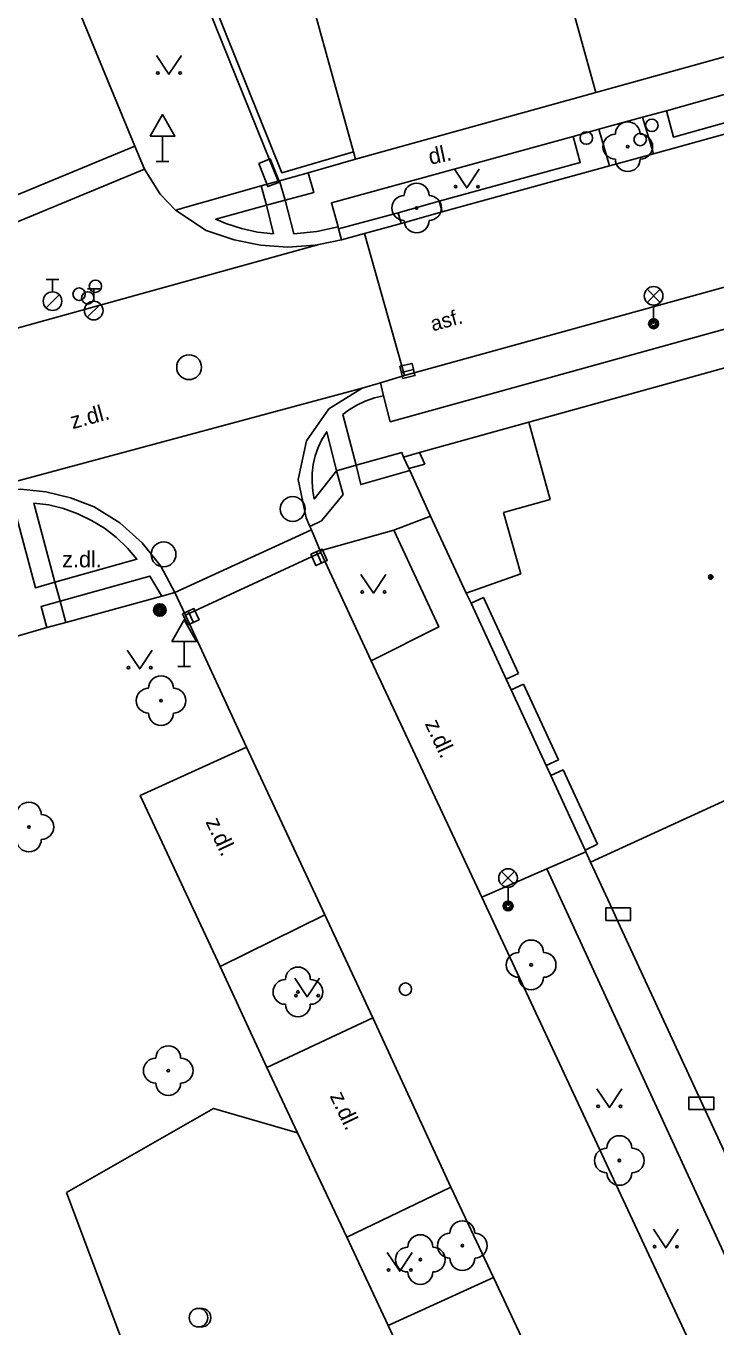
# Model space of a CAD drawing. Extents: x -595546 to -593986, y -1160845 to -1159202.
# Drawn here: x -595314.5 to -595286.7, y -1160633.9 to -1160581.5 of the extents above; entities that cross this region are included whole.
import ezdxf

# ---------------------------------------------------------------- set-up
doc = ezdxf.new("R2010")
doc.units = 0
for name, color, linetype in [('Level 22', 7, 'Continuous'), ('Level 24', 7, 'Continuous'), ('Level 25', 7, 'Continuous'), ('Level 27', 7, 'Continuous'), ('Level 28', 7, 'Continuous'), ('Level 33', 7, 'Continuous'), ('Level 34', 7, 'Continuous'), ('Level 36', 7, 'Continuous'), ('Level 39', 7, 'Continuous'), ('Specificka linie pasportu komunikaci', 7, 'Continuous'), ('TM - budovy zdene_ betonove - NP', 7, 'Continuous'), ('TM - budovy zdene_ betonove - VP', 7, 'Continuous'), ('TM - chodniky - VP', 7, 'Continuous'), ('TM - komunikace - VP', 7, 'Continuous'), ('TM - plot drateny_ kovovy - VP', 7, 'Continuous'), ('TM - podezdivka plotu - VP', 7, 'Continuous'), ('TM - popis povrchu', 7, 'Continuous'), ('TM - rozhrani mezi zpev. plochami mezi sebou - VP', 7, 'Continuous'), ('TM - rozhrani ploch obecne - VP', 7, 'Continuous')]:
    doc.layers.add(name, color=color, linetype=linetype)

msp = doc.modelspace()

# ---------------------------------------------------------------- linework, layer by layer
at = {"layer": 'Level 22'}
for centre in [(-595290.28, -1160586.33), (-595298.78, -1160588.8), (-595309.07, -1160608.64), (-595314.39, -1160613.73), (-595294.17, -1160619.28), (-595303.56, -1160620.37), (-595308.78, -1160623.54), (-595290.62, -1160627.16), (-595296.94, -1160630.59), (-595298.63, -1160631.15)]:
    msp.add_circle(centre, 0.05, dxfattribs=at)
for centre, start, end in [((-595290.28, -1160585.83), 0, 180), ((-595290.78, -1160586.33), 90, 270), ((-595289.78, -1160586.33), 270, 90), ((-595290.28, -1160586.83), 180, 0), ((-595299.28, -1160588.8), 90, 270), ((-595298.78, -1160588.3), 0, 180), ((-595298.28, -1160588.8), 270, 90), ((-595298.78, -1160589.3), 180, 0), ((-595309.07, -1160608.14), 0, 180), ((-595309.57, -1160608.64), 90, 270), ((-595308.57, -1160608.64), 270, 90), ((-595309.07, -1160609.14), 180, 0), ((-595314.39, -1160613.23), 0, 180), ((-595313.89, -1160613.73), 270, 90), ((-595314.39, -1160614.23), 180, 0), ((-595294.17, -1160618.78), 0, 180), ((-595294.67, -1160619.28), 90, 270), ((-595293.67, -1160619.28), 270, 90), ((-595303.56, -1160619.87), 0, 180), ((-595304.06, -1160620.37), 90, 270), ((-595303.06, -1160620.37), 270, 90), ((-595294.17, -1160619.78), 180, 0), ((-595303.56, -1160620.87), 180, 0), ((-595308.78, -1160623.04), 0, 180), ((-595309.28, -1160623.54), 90, 270), ((-595308.28, -1160623.54), 270, 90), ((-595308.78, -1160624.04), 180, 0), ((-595290.62, -1160626.66), 0, 180), ((-595291.12, -1160627.16), 90, 270), ((-595290.12, -1160627.16), 270, 90), ((-595290.62, -1160627.66), 180, 0), ((-595296.94, -1160630.09), 0, 180), ((-595298.63, -1160630.65), 0, 180), ((-595297.44, -1160630.59), 90, 270), ((-595296.44, -1160630.59), 270, 90), ((-595299.13, -1160631.15), 90, 270), ((-595298.13, -1160631.15), 270, 90), ((-595296.94, -1160631.09), 180, 0), ((-595298.63, -1160631.65), 180, 0)]:
    msp.add_arc(centre, 0.5, start, end, dxfattribs=at)
at = {"layer": 'Level 24'}
for points in [[(-595305.137, -1160587.007), (-595304.768, -1160587.937), (-595304.303, -1160587.753), (-595304.672, -1160586.823)], [(-595291.167, -1160617.488), (-595290.167, -1160617.488), (-595290.167, -1160616.988), (-595291.167, -1160616.988)], [(-595287.818, -1160625.109), (-595286.818, -1160625.109), (-595286.818, -1160624.609), (-595287.818, -1160624.609)]]:
    msp.add_lwpolyline(points, close=True, dxfattribs=at)
at = {"layer": 'Level 25'}
for radius in [0.25, 0.2, 0.15, 0.1, 0.05]:
    msp.add_circle((-595309.12, -1160604.99), radius, dxfattribs=at)
at = {"layer": 'Level 27'}
for p, q in [((-595299.393, -1160595.418), (-595298.907, -1160595.302)), ((-595302.814, -1160602.643), (-595302.606, -1160603.097)), ((-595307.974, -1160605.033), (-595307.766, -1160605.487))]:
    msp.add_line(p, q, dxfattribs=at)
for points in [[(-595299.335, -1160595.662), (-595298.848, -1160595.545), (-595298.965, -1160595.058), (-595299.452, -1160595.175)], [(-595303.041, -1160602.747), (-595302.833, -1160603.201), (-595302.379, -1160602.993), (-595302.587, -1160602.539)], [(-595308.201, -1160605.137), (-595307.993, -1160605.591), (-595307.539, -1160605.383), (-595307.747, -1160604.929)]]:
    msp.add_lwpolyline(points, close=True, dxfattribs=at)
for centre in [(-595307.94, -1160595.21), (-595303.77, -1160600.92), (-595308.97, -1160602.75)]:
    msp.add_circle(centre, 0.5, dxfattribs=at)
at = {"layer": 'Level 28'}
for p, q in [((-595313.69, -1160591.675), (-595313.19, -1160591.675)), ((-595313.44, -1160592.175), (-595313.44, -1160591.675)), ((-595313.698, -1160592.822), (-595313.168, -1160592.292)), ((-595312.03, -1160592.055), (-595311.53, -1160592.055)), ((-595311.78, -1160592.555), (-595311.78, -1160592.055)), ((-595312.038, -1160593.202), (-595311.508, -1160592.672))]:
    msp.add_line(p, q, dxfattribs=at)
for centre, radius in [((-595289.31, -1160585.47), 0.25), ((-595291.95, -1160585.98), 0.25), ((-595289.78, -1160586.04), 0.25), ((-595311.71, -1160591.95), 0.25), ((-595313.44, -1160592.55), 0.375), ((-595312.37, -1160592.27), 0.25), ((-595312.02, -1160592.42), 0.25), ((-595311.78, -1160592.93), 0.375), ((-595299.23, -1160620.26), 0.25)]:
    msp.add_circle(centre, radius, dxfattribs=at)
at = {"layer": 'Level 33'}
for p, q in [((-595289.505, -1160592.6), (-595288.975, -1160592.07)), ((-595289.505, -1160592.07), (-595288.975, -1160592.6)), ((-595289.24, -1160592.71), (-595289.24, -1160593.46)), ((-595295.365, -1160616.05), (-595294.835, -1160615.52)), ((-595295.365, -1160615.52), (-595294.835, -1160616.05)), ((-595295.1, -1160616.16), (-595295.1, -1160616.91))]:
    msp.add_line(p, q, dxfattribs=at)
for centre, radius in [((-595289.24, -1160592.335), 0.375), ((-595289.24, -1160593.46), 0.2), ((-595289.24, -1160593.46), 0.145), ((-595289.24, -1160593.46), 0.0876), ((-595295.1, -1160615.785), 0.375), ((-595295.1, -1160616.91), 0.2), ((-595295.1, -1160616.91), 0.145), ((-595295.1, -1160616.91), 0.0876)]:
    msp.add_circle(centre, radius, dxfattribs=at)
at = {"layer": 'Level 34'}
for p, q in [((-595309.01, -1160585.902), (-595309.01, -1160586.92)), ((-595309.26, -1160586.92), (-595308.76, -1160586.92)), ((-595308.14, -1160606.252), (-595308.14, -1160607.27)), ((-595308.39, -1160607.27), (-595307.89, -1160607.27))]:
    msp.add_line(p, q, dxfattribs=at)
for points in [[(-595309.51, -1160585.902), (-595308.51, -1160585.902), (-595309.01, -1160585.036)], [(-595308.64, -1160606.252), (-595307.64, -1160606.252), (-595308.14, -1160605.386)]]:
    msp.add_lwpolyline(points, close=True, dxfattribs=at)
at = {"layer": 'Level 36'}
for points in [[(-595309.25, -1160582.66), (-595308.75, -1160583.41), (-595308.25, -1160582.66)], [(-595297.26, -1160587.24), (-595296.76, -1160587.99), (-595296.26, -1160587.24)], [(-595301.02, -1160603.56), (-595300.52, -1160604.31), (-595300.02, -1160603.56)], [(-595310.43, -1160606.61), (-595309.93, -1160607.36), (-595309.43, -1160606.61)], [(-595303.69, -1160619.82), (-595303.19, -1160620.57), (-595302.69, -1160619.82)], [(-595291.52, -1160624.28), (-595291.02, -1160625.03), (-595290.52, -1160624.28)], [(-595289.25, -1160629.93), (-595288.75, -1160630.68), (-595288.25, -1160629.93)], [(-595299.96, -1160630.87), (-595299.46, -1160631.62), (-595298.96, -1160630.87)]]:
    msp.add_lwpolyline(points, dxfattribs=at)
for centre, radius in [((-595309.2, -1160583.36), 0.05), ((-595308.301, -1160583.36), 0.05), ((-595297.21, -1160587.94), 0.05), ((-595296.311, -1160587.94), 0.05), ((-595300.97, -1160604.26), 0.05), ((-595300.071, -1160604.26), 0.05), ((-595310.38, -1160607.31), 0.05), ((-595309.481, -1160607.31), 0.05), ((-595303.64, -1160620.52), 0.05), ((-595302.741, -1160620.52), 0.05), ((-595291.47, -1160624.98), 0.05), ((-595290.571, -1160624.98), 0.05), ((-595289.2, -1160630.63), 0.05), ((-595288.301, -1160630.63), 0.05), ((-595299.91, -1160631.57), 0.05), ((-595299.011, -1160631.57), 0.05), ((-595307.56, -1160633.49), 0.375)]:
    msp.add_circle(centre, radius, dxfattribs=at)
msp.add_arc((-595307.435, -1160633.49), 0.375, 260.4059, 99.5941, dxfattribs=at)
at = {"layer": 'Level 39'}
for radius in [0.09, 0.0398]:
    msp.add_circle((-595286.94, -1160603.66), radius, dxfattribs=at)
at = {"layer": 'Specificka linie pasportu komunikaci'}
for points in [[(-595299.52, -1160588.99), (-595297.87, -1160588.53)], [(-595318.16, -1160594.55), (-595302.72, -1160590.269)], [(-595316.34, -1160600.19), (-595300.97, -1160596.06)], [(-595293.54, -1160615.42), (-595291.97, -1160614.73)], [(-595306.69, -1160619.35), (-595304.81, -1160623.41)], [(-595301.59, -1160630.25), (-595299.93, -1160633.8)]]:
    msp.add_lwpolyline(points, dxfattribs=at)
at = {"layer": 'TM - budovy zdene_ betonove - NP'}
for points in [[(-595293.4, -1160600.54), (-595294.26, -1160597.42)], [(-595298.45, -1160599.11), (-595298.67, -1160598.65)], [(-595299.1, -1160599.29), (-595298.45, -1160599.11)], [(-595295.28, -1160601.06), (-595293.4, -1160600.54)], [(-595294.59, -1160603.53), (-595295.28, -1160601.06)], [(-595296.78, -1160604.31), (-595294.59, -1160603.53)], [(-595296.09, -1160604.49), (-595296.59, -1160604.72)], [(-595294.68, -1160607.55), (-595296.09, -1160604.49)], [(-595295.18, -1160607.78), (-595294.68, -1160607.55)], [(-595294.48, -1160607.97), (-595294.98, -1160608.2)], [(-595293.07, -1160611.02), (-595294.48, -1160607.97)], [(-595293.57, -1160611.25), (-595293.07, -1160611.02)], [(-595292.88, -1160611.43), (-595293.38, -1160611.66)], [(-595291.5, -1160614.42), (-595292.88, -1160611.43)], [(-595292, -1160614.66), (-595291.5, -1160614.42)]]:
    msp.add_lwpolyline(points, dxfattribs=at)
at = {"layer": 'TM - budovy zdene_ betonove - VP'}
for points in [[(-595291.57, -1160584.15), (-595294.1, -1160574.98)], [(-595304.31, -1160575.72), (-595301.32, -1160586.54)], [(-595284.36, -1160582.15), (-595291.57, -1160584.15)], [(-595291.57, -1160584.15), (-595301.24, -1160586.83)], [(-595301.32, -1160586.54), (-595301.24, -1160586.83)], [(-595280.22, -1160593.53), (-595294.26, -1160597.42)], [(-595298.67, -1160598.65), (-595294.26, -1160597.42)], [(-595299.31, -1160598.83), (-595298.67, -1160598.65)], [(-595299.1, -1160599.29), (-595299.31, -1160598.83)], [(-595299.06, -1160599.37), (-595299.1, -1160599.29)], [(-595298.22, -1160601.21), (-595299.06, -1160599.37)], [(-595296.78, -1160604.31), (-595298.22, -1160601.21)], [(-595296.59, -1160604.72), (-595296.78, -1160604.31)], [(-595296.59, -1160604.72), (-595295.18, -1160607.78)], [(-595294.98, -1160608.2), (-595295.18, -1160607.78)], [(-595294.98, -1160608.2), (-595293.57, -1160611.25)], [(-595291.78, -1160615.14), (-595281.48, -1160610.42)], [(-595293.38, -1160611.66), (-595293.57, -1160611.25)], [(-595293.38, -1160611.66), (-595292, -1160614.66)], [(-595291.97, -1160614.73), (-595292, -1160614.66)], [(-595291.78, -1160615.14), (-595291.97, -1160614.73)], [(-595290.91, -1160617.02), (-595291.78, -1160615.14)], [(-595290.66, -1160617.56), (-595290.91, -1160617.02)], [(-595286.32, -1160626.96), (-595290.66, -1160617.56)]]:
    msp.add_lwpolyline(points, dxfattribs=at)
at = {"layer": 'TM - chodniky - VP'}
for points in [[(-595288.72, -1160584.88), (-595283.88, -1160583.52), (-595273.57, -1160580.68)], [(-595291.44, -1160585.63), (-595289.69, -1160585.14)], [(-595289.69, -1160585.14), (-595288.72, -1160584.88)], [(-595292.48, -1160585.92), (-595291.44, -1160585.63)], [(-595301.94, -1160589.56), (-595302.21, -1160588.59), (-595292.48, -1160585.92)], [(-595304.35, -1160587.72), (-595305.04, -1160587.91)], [(-595305.04, -1160587.91), (-595308.49, -1160588.88)], [(-595300.11, -1160596.36), (-595299.84, -1160597.41), (-595280.67, -1160592.09), (-595274.47, -1160590.35), (-595274.87, -1160588.8)], [(-595301.92, -1160589.64), (-595301.94, -1160589.56)], [(-595301.8, -1160590.08), (-595301.92, -1160589.64)], [(-595300.23, -1160595.84), (-595300.11, -1160596.36)], [(-595299.7, -1160601.78), (-595302.67, -1160602.61)], [(-595300.61, -1160607.03), (-595297.89, -1160605.67), (-595299.7, -1160601.78)], [(-595312.9, -1160605.49), (-595309.04, -1160604.43)], [(-595309.04, -1160604.43), (-595308.51, -1160604.29)], [(-595313.67, -1160605.7), (-595312.9, -1160605.49)], [(-595313.67, -1160605.7), (-595315, -1160606.09)], [(-595293.54, -1160615.42), (-595296.16, -1160616.56)], [(-595282.79, -1160638.75), (-595293.54, -1160615.42)]]:
    msp.add_lwpolyline(points, dxfattribs=at)
at = {"layer": 'TM - komunikace - VP'}
for points in [[(-595313.14, -1160578.98), (-595310.13, -1160586.31)], [(-595265.41, -1160580), (-595289.25, -1160586.62)], [(-595310.13, -1160586.31), (-595309.73, -1160587.24)], [(-595289.25, -1160586.62), (-595291.02, -1160587.1)], [(-595308.49, -1160588.88), (-595309.1, -1160588.24), (-595309.73, -1160587.24)], [(-595291.02, -1160587.1), (-595297.75, -1160588.96)], [(-595299.27, -1160595.54), (-595274.87, -1160588.8)], [(-595302.72, -1160590.27), (-595302.87, -1160590.3), (-595303.97, -1160590.37), (-595305.06, -1160590.3), (-595306.13, -1160590.08), (-595307.25, -1160589.7), (-595308.49, -1160588.88)], [(-595297.75, -1160588.96), (-595299.4, -1160589.42)], [(-595300.88, -1160589.83), (-595301.8, -1160590.08)], [(-595299.4, -1160589.42), (-595300.88, -1160589.83)], [(-595301.8, -1160590.08), (-595302.72, -1160590.27)], [(-595300.23, -1160595.84), (-595299.27, -1160595.54)], [(-595303.08, -1160601.62), (-595303.23, -1160601.28), (-595303.55, -1160599.73), (-595303.22, -1160598.18), (-595302.31, -1160596.89), (-595300.97, -1160596.06)], [(-595300.97, -1160596.06), (-595300.23, -1160595.84)], [(-595315.76, -1160600.14), (-595314.73, -1160600.12), (-595313.71, -1160600.23), (-595312.72, -1160600.47), (-595311.76, -1160600.84), (-595310.73, -1160601.48), (-595309.83, -1160602.28), (-595309.08, -1160603.23), (-595308.51, -1160604.29)], [(-595303.01, -1160601.76), (-595303.08, -1160601.62)], [(-595302.67, -1160602.61), (-595303.01, -1160601.76)], [(-595302.64, -1160602.68), (-595302.67, -1160602.61)], [(-595300.61, -1160607.03), (-595302.64, -1160602.68)], [(-595308.51, -1160604.29), (-595308.09, -1160605.2)], [(-595308.09, -1160605.2), (-595305.63, -1160610.51)], [(-595296.16, -1160616.56), (-595300.61, -1160607.03)], [(-595305.63, -1160610.51), (-595309.91, -1160612.46), (-595308.73, -1160614.98)], [(-595308.73, -1160614.98), (-595306.69, -1160619.35)], [(-595285.26, -1160639.9), (-595296.16, -1160616.56)], [(-595306.69, -1160619.35), (-595302.48, -1160617.27)], [(-595302.48, -1160617.27), (-595300.54, -1160621.42)], [(-595300.54, -1160621.42), (-595304.81, -1160623.41)], [(-595304.81, -1160623.41), (-595303.57, -1160626.05)], [(-595303.57, -1160626.05), (-595301.59, -1160630.25)], [(-595301.59, -1160630.25), (-595297.4, -1160628.23)], [(-595297.4, -1160628.23), (-595295.68, -1160631.87)], [(-595295.68, -1160631.87), (-595299.93, -1160633.8)], [(-595299.93, -1160633.8), (-595297.95, -1160638.05)]]:
    msp.add_lwpolyline(points, dxfattribs=at)
at = {"layer": 'TM - plot drateny_ kovovy - VP'}
msp.add_lwpolyline([(-595301.32, -1160586.54), (-595304.21, -1160587.38), (-595308.32, -1160577.13)], dxfattribs=at)
at = {"layer": 'TM - podezdivka plotu - VP'}
for points in [[(-595304.35, -1160587.72), (-595308.58, -1160577.24)], [(-595303.15, -1160587.38), (-595301.24, -1160586.83)], [(-595304.35, -1160587.72), (-595304.3, -1160587.7)], [(-595304.3, -1160587.7), (-595303.15, -1160587.38)]]:
    msp.add_lwpolyline(points, dxfattribs=at)
at = {"layer": 'TM - rozhrani mezi zpev. plochami mezi sebou - VP'}
for points in [[(-595304.3, -1160587.7), (-595304.07, -1160588.48)], [(-595304.07, -1160588.48), (-595302.92, -1160588.18), (-595303.15, -1160587.38)], [(-595305.04, -1160587.91), (-595304.83, -1160588.69)], [(-595304.83, -1160588.69), (-595306.87, -1160589.25), (-595306.46, -1160589.43), (-595305.83, -1160589.63), (-595305.19, -1160589.77), (-595304.54, -1160589.84)], [(-595304.83, -1160588.69), (-595304.07, -1160588.48)], [(-595304.54, -1160589.84), (-595304.83, -1160588.69)], [(-595301.94, -1160589.56), (-595302.8, -1160589.74), (-595303.72, -1160589.84), (-595304.07, -1160588.48)], [(-595301.22, -1160599.15), (-595301.75, -1160597.11), (-595301.52, -1160596.94), (-595301.19, -1160596.74), (-595300.85, -1160596.58), (-595300.48, -1160596.45), (-595300.11, -1160596.36)], [(-595302, -1160599.38), (-595302.4, -1160597.81), (-595302.59, -1160598.12), (-595302.74, -1160598.44), (-595302.86, -1160598.78), (-595302.94, -1160599.13), (-595302.98, -1160599.49), (-595302.99, -1160599.84), (-595302.96, -1160600.2), (-595302.9, -1160600.52)], [(-595299.31, -1160598.83), (-595299.37, -1160598.65), (-595301.22, -1160599.15)], [(-595301.22, -1160599.15), (-595302, -1160599.38)], [(-595301.22, -1160599.15), (-595301.03, -1160599.94), (-595299.15, -1160599.4), (-595299.06, -1160599.37)], [(-595302.9, -1160600.52), (-595302, -1160599.38)], [(-595302, -1160599.38), (-595301.74, -1160600.34)], [(-595301.74, -1160600.34), (-595302.61, -1160601.4)], [(-595313.34, -1160603.87), (-595314.13, -1160604.09), (-595315.04, -1160600.67), (-595315.6, -1160600.73)], [(-595313.34, -1160603.87), (-595310.04, -1160602.94), (-595310.42, -1160602.5), (-595310.86, -1160602.07), (-595311.34, -1160601.7), (-595311.87, -1160601.38), (-595312.42, -1160601.11), (-595312.99, -1160600.9), (-595313.59, -1160600.76), (-595314.19, -1160600.68), (-595313.34, -1160603.87)], [(-595302.61, -1160601.4), (-595303.08, -1160601.62)], [(-595313.13, -1160604.64), (-595313.34, -1160603.87)], [(-595309.04, -1160604.43), (-595309.52, -1160603.62), (-595313.13, -1160604.64)], [(-595313.67, -1160605.7), (-595313.9, -1160604.85), (-595313.13, -1160604.64)], [(-595312.9, -1160605.49), (-595313.13, -1160604.64)], [(-595302.48, -1160617.27), (-595305.63, -1160610.51)], [(-595297.4, -1160628.23), (-595300.54, -1160621.42)], [(-595292.49, -1160638.68), (-595295.68, -1160631.87)]]:
    msp.add_lwpolyline(points, dxfattribs=at)
at = {"layer": 'TM - rozhrani ploch obecne - VP'}
for points in [[(-595273.57, -1160580.68), (-595273.3, -1160581.71), (-595283.36, -1160584.52), (-595288.44, -1160585.94), (-595288.72, -1160584.88)], [(-595289.69, -1160585.14), (-595289.25, -1160586.62)], [(-595291.44, -1160585.63), (-595291.02, -1160587.1)], [(-595292.48, -1160585.92), (-595292.19, -1160586.96), (-595297.87, -1160588.53)], [(-595315.68, -1160588.6), (-595310.13, -1160586.31)], [(-595309.73, -1160587.24), (-595315.31, -1160589.54)], [(-595297.87, -1160588.53), (-595297.75, -1160588.96)], [(-595299.52, -1160588.99), (-595301.92, -1160589.64)], [(-595299.4, -1160589.42), (-595299.52, -1160588.99)], [(-595300.88, -1160589.83), (-595299.27, -1160595.54)], [(-595299.7, -1160601.78), (-595298.22, -1160601.21)], [(-595308.51, -1160604.29), (-595303.01, -1160601.76)], [(-595308.09, -1160605.2), (-595302.64, -1160602.68)], [(-595312.87, -1160628.45), (-595306.96, -1160625.07), (-595303.57, -1160626.05)], [(-595297.95, -1160638.05), (-595309.24, -1160638.15), (-595312.87, -1160628.45)]]:
    msp.add_lwpolyline(points, dxfattribs=at)

# ---------------------------------------------------------------- texts
at = {"layer": 'TM - popis povrchu'}
for s, height, rotation, p in [('dl.', 0.65, 12.1, (-595298.23, -1160587.06)), ('asf.', 0.6, 15.2551, (-595298.13, -1160593.77)), ('z.dl.', 0.65, 15.2551, (-595312.63, -1160597.71)), ('z.dl.', 0.65, 295.0499, (-595298.46, -1160609.57)), ('z.dl.', 0.65, 295.054, (-595307.29, -1160613.52)), ('z.dl.', 0.65, 295.3644, (-595302.29, -1160624.56))]:
    msp.add_text(s, height=height, rotation=rotation, dxfattribs=at).set_placement(p)
msp.add_text('z.dl.', height=0.65, dxfattribs=at).set_placement((-595313.05, -1160603.27))

doc.saveas('drawing.dxf')
